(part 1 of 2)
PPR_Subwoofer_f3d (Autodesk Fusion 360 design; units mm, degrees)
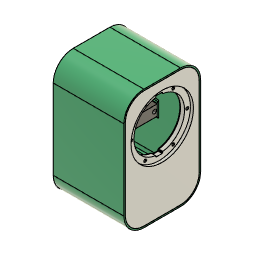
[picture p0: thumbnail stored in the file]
parameter "width" = 115
parameter "height" = 180
parameter "depth" = 94
parameter "cornerradius" = 30
parameter "driveroffset" = 60
parameter "length" = 150
parameter "width_1" = 84
parameter "cornerradius_1" = 40
parameter "length_1" = 155
parameter "width_2" = 89
parameter "cornerradius_2" = 44
sketch "Sketch1" plane through (0, 0, 0) normal (1, 0, 0) x axis (0, 1, 0)
  line L1 (85, 0) -> (30, 0)
  line L2 (115, 150) -> (115, 30)
  line L3 (30, 180) -> (85, 180)
  line L4 (0, 30) -> (0, 150)
  line L5 (10, 30) -> (10, 150)
  line L6 (85, 10) -> (30, 10)
  line L7 (105, 150) -> (105, 30)
  line L8 (30, 170) -> (85, 170)
  line L9 (85, 2) -> (30, 2)
  line L10 (113, 150) -> (113, 30)
  line L11 (30, 178) -> (85, 178)
  line L12 (2, 30) -> (2, 150)
  arc A1 centre (30, 150) radius 30 clockwise from (0, 150) to (30, 180)
  arc A2 centre (85, 150) radius 30 clockwise from (85, 180) to (115, 150)
  arc A3 centre (85, 30) radius 30 clockwise from (115, 30) to (85, 0)
  arc A4 centre (30, 30) radius 30 clockwise from (30, 0) to (0, 30)
  arc A5 centre (30, 30) radius 20 clockwise from (30, 10) to (10, 30)
  arc A6 centre (85, 30) radius 20 clockwise from (105, 30) to (85, 10)
  arc A7 centre (85, 150) radius 20 clockwise from (85, 170) to (105, 150)
  arc A8 centre (30, 150) radius 20 clockwise from (10, 150) to (30, 170)
  arc A9 centre (30, 30) radius 28 clockwise from (30, 2) to (2, 30)
  arc A10 centre (85, 30) radius 28 clockwise from (113, 30) to (85, 2)
  arc A11 centre (85, 150) radius 28 clockwise from (85, 178) to (113, 150)
  arc A12 centre (30, 150) radius 28 clockwise from (2, 150) to (30, 178)
  point P1 (0, 0)
  point P2 (0, 0)
  point P4 (0, 180)
  point P3 (115, 0)
  horizontal L1
  vertical L2
  horizontal L3
  vertical L4
  coincident P1 P2
  coincident P4 L3
  coincident P4 L4
  tangent L3 A1
  tangent L4 A1
  tangent L2 A2
  tangent L3 A2
  equal A1 A2
  coincident P3 L1
  coincident P3 L2
  tangent L1 A3
  tangent L2 A3
  equal A1 A3
  coincident P2 L1
  coincident P2 L4
  tangent L1 A4
  tangent L4 A4
  equal A1 A4
  dimension "d6" distance P2 P3 = 115 (= "width")
  dimension "d7" distance P2 P4 = 180 (= "height")
  dimension "d8" radius A1 = 30 (= "cornerradius")
  dimension "d9" = -10
  dimension "d10" = -2
extrude "Extrude1" new body sketch "Sketch1" profile of L5 A5 L7 L6 A6 L8 A7 A8 along normal blind 10
extrude "Extrude2" add sketch "Sketch1" along normal blind 94 (= "depth")
extrude "Extrude3" sketch "Sketch1" profile of L1 L2 L3 L4 A1 A2 A3 A4 A9 L10 L9 A10 L11 A11 A12 L12 blind 12
extrude "Extrude4" new body of existing geometry to an object bodies "Internal volume"
sketch "Sketch1" plane through (0, 0, 0) normal (1, 0, 0) x axis (0, 1, 0)
  line L1 (113, 150) -> (113, 30)
  line L2 (85, 2) -> (30, 2)
  line L3 (2, 30) -> (2, 150)
  line L4 (57.5, 2) -> (57.5, 178)
  line L5 (15.5, 118) -> (57.5, 118)
  line L6 (30, 178) -> (85, 178)
  line L7 (85, 2.2) -> (30, 2.2)
  line L8 (112.8, 150) -> (112.8, 30)
  line L9 (30, 177.8) -> (85, 177.8)
  line L10 (2.2, 30) -> (2.2, 150)
  line L11 (52.5, 157.8) -> (62.5, 157.8)
  line L12 (52.5, 78.2) -> (52.5, 157.8)
  line L13 (62.5, 78.2) -> (52.5, 78.2)
  line L14 (62.5, 157.8) -> (62.5, 78.2)
  line L15 (52.5, 78.2) -> (62.5, 157.8)
  line L16 (62.5, 78.2) -> (52.5, 157.8)
  arc A1 centre (30, 150) radius 28 clockwise from (2, 150) to (30, 178)
  arc A2 centre (85, 150) radius 28 clockwise from (85, 178) to (113, 150)
  arc A3 centre (85, 30) radius 28 clockwise from (113, 30) to (85, 2)
  arc A4 centre (30, 30) radius 28 clockwise from (30, 2) to (2, 30)
  circle C1 centre (57.5, 118) radius 46.8
  circle C2 centre (57.5, 118) radius 38
  circle C3 centre (15.5, 118) radius 1.35
  circle C4 centre (36.5, 81.6269) radius 1.35
  circle C5 centre (78.5, 81.6269) radius 1.35
  circle C6 centre (99.5, 118) radius 1.35
  circle C7 centre (78.5, 154.3731) radius 1.35
  circle C8 centre (36.5, 154.3731) radius 1.35
  arc A5 centre (30, 30) radius 27.8 clockwise from (30, 2.2) to (2.2, 30)
  arc A6 centre (85, 30) radius 27.8 clockwise from (112.8, 30) to (85, 2.2)
  arc A7 centre (85, 150) radius 27.8 clockwise from (85, 177.8) to (112.8, 150)
  arc A8 centre (30, 150) radius 27.8 clockwise from (2.2, 150) to (30, 177.8)
  point P21 (57.5, 2)
  point P22 (57.5, 118)
  point P24 (57.5, 118)
  point P25 (15.5, 118)
  point P26 (15.5, 118)
  point P20 (57.5, 178)
  point P50 (57.5, 118)
  point P23 (57.5, 118)
  point P48 (52.5, 78.2)
  point P49 (62.5, 78.2)
  point P47 (52.5, 157.8)
  midpoint L2 P21
  coincident L4 P22
  concentric C1 C2
  coincident P22 P24
  coincident P25 P26
  coincident P20 L6
  midpoint P20 L6
  horizontal L11
  perpendicular L11 L12
  parallel L11 L13
  parallel L12 L14
  coincident L15 P50
  coincident L16 P50
  coincident P23 P50
  dimension "d21" diameter C1 = 93.6
  dimension "d23" diameter C2 = 76
  dimension "d24" angle L4 L5 = 90
  dimension "d25" distance P24 P25 = 42 (= "( 84 / 2 ) * 1 mm")
  dimension "d26" diameter C3 = 2.7
  dimension "d36" = -0.2
  dimension "d37" distance L5 L6 = 60 (= "driveroffset")
  dimension "d180" distance P48 P49 = 10
  dimension "d181" distance P47 P48 = 79.6
  dimension "d28" C-Pattern1-Angle = 360
extrude "Extrude1" sketch "Sketch1" profile of C1 C2 C3 C4 C5 C6 C7 C8 L7 A5 A8 L9 A6 L8 A7 L10 L11 L12 L13 L14 blind 12
extrude "Extrude2" sketch "Sketch1" profile of C1 C2 C3 C4 C5 C6 C7 C8 blind -4.5
chamfer "Chamfer1" distance 0.8
sketch "Sketch1" plane through (0, 0, 0) normal (1, 0, 0) x axis (0, 1, 0)
  line L1 (0, 0.6) -> (4, 0.6)
  line L2 (4, 0) -> (0, 0)
  line L3 (-1.2, 4) -> (-1.2, 0)
  line L4 (0, 0) -> (0, 4)
  line L5 (-1.2, 0) -> (0, 0)
  line L6 (0, 0) -> (0, 0.6)
  line L7 (4, 0.6) -> (4, 0)
  line L8 (0, 4) -> (-1.2, 4)
  line L9 (-1.2, 0) -> (-1.2, 0.6)
  line L10 (-3.6, 2.3835) -> (-1.6, 0)
  line L11 (1.0702, 0) -> (-1.6, 0)
  line L12 (-1.2, 0) -> (-3.2, 2.3835)
  line L13 (-5.6, 0) -> (-3.6, 2.3835)
  line L14 (-4, 2.3835) -> (-6, 0)
  line L15 (-6, 0) -> (-5.6, 0)
  line L16 (-1.2, 0) -> (-1.6, 0)
  line L17 (-4, 2.3835) -> (-3.2, 2.3835)
  line L18 (-4, 2.9835) -> (-4, 2.3835)
  line L19 (-3.2, 2.9835) -> (-4, 2.9835)
  line L20 (-3.2, 2.3835) -> (-3.2, 2.9835)
  line L21 (-6, 0.4) -> (-6, 0)
  line L22 (-5.6644, 0.4) -> (-6, 0.4)
  line L23 (-1.2, 0.4) -> (-1.5356, 0.4)
  line L24 (-8.8, 2.3835) -> (-10.8, 0)
  line L25 (-10.4, 0) -> (-8.4, 2.3835)
  line L26 (-10.4644, 0.4) -> (-10.8, 0.4)
  line L27 (-10.8, 0) -> (-10.4, 0)
  line L28 (-6, 0) -> (-6.4, 0)
  line L29 (-8.4, 2.3835) -> (-6.4, 0)
  line L30 (-6, 0) -> (-8, 2.3835)
  line L31 (-6, 0.4) -> (-6.3356, 0.4)
  line L32 (-8, 2.3835) -> (-8, 2.9835)
  line L33 (-8, 2.9835) -> (-8.8, 2.9835)
  line L34 (-8.8, 2.9835) -> (-8.8, 2.3835)
  line L35 (-6, 2.4) -> (-6, 0.4)
  line L36 (-10.8, 4) -> (-10.8, 0)
  line L37 (-12, 0) -> (-12, 4)
  line L38 (-12, 0.6) -> (-16, 0.6)
  line L39 (-16, 0) -> (-12, 0)
  line L40 (-10.8, 0) -> (-12, 0)
  line L41 (-16, 0.6) -> (-16, 0)
  line L42 (-12, 4) -> (-10.8, 4)
  line L43 (-44.5, 10) -> (-44.5, 0)
  point P5 (0, 0)
  point P10 (0, 0)
  point P9 (0, 0)
  point P1 (0, 0)
  point P16 (-1.2, 0)
  point P13 (-3.6, 2.3835)
  point P15 (-3.2, 2.3835)
  point P19 (-4, 2.3835)
  point P17 (-5.6, 0)
  point P18 (-6, 0)
  point P11 (-1.6, 0)
  point P24 (-5.6644, 0.4)
  point P25 (-1.5356, 0.4)
  point P26 (-1.2, 0.4)
  point P2 (0, 0.6)
  point P47 (-12, 0.6)
  point P3 (4, 0)
  point P49 (-16, 0)
  point P4 (4, 0.6)
  point P46 (-16, 0.6)
  point P45 (-12, 0)
  point P6 (0, 4)
  point P44 (-12, 4)
  point P7 (-1.2, 4)
  point P43 (-10.8, 4)
  point P8 (-1.2, 0)
  point P42 (-10.8, 0)
  point P48 (-12, 0)
  point P12 (-1.2, 0.6)
  point P22 (-3.2, 2.9835)
  point P23 (-6, 0.4)
  point P37 (-6, 0.4)
  point P41 (-6, 2.4)
  point P50 (-44.5, 0)
  point P51 (-44.5, 10)
  horizontal L5
  vertical L3
  horizontal L8
  vertical L4
  coincident P5 P10
  horizontal L2
  vertical L7
  horizontal L1
  vertical L6
  coincident P9 P10
  coincident P1 P9
  vertical L9
  horizontal L11
  coincident L11 P16
  parallel L10 L12
  horizontal P13 P15
  horizontal P13 P19
  horizontal P17 P18
  equal L13 L14
  horizontal P9 P11
  coincident P9 L15
  horizontal L17
  vertical L18
  horizontal L19
  vertical L20
  coincident P19 L18
  vertical L21
  coincident L14 P24
  perpendicular L21 L22
  coincident L12 P25
  horizontal L23
  vertical P16 P26
  symmetric P2 L35 P47
  symmetric P3 L35 P49
  symmetric P4 L35 P46
  symmetric P5 L35 P45
  symmetric P6 L35 P44
  symmetric P7 L35 P43
  symmetric P8 L35 P42
  symmetric P9 L35 P48
  perpendicular L38 L43
  vertical L35
  dimension "d5" distance P6 P7 = 1.2
  dimension "d6_1" distance P5 P6 = 4
  dimension "d7_1" distance P3 P9 = 4
  dimension "d8_1" distance P2 P9 = 0.6
  dimension "d9_1" distance P8 P11 = 0.4
  dimension "d10_1" distance P8 P12 = 0.6
  dimension "d11_1" angle L10 L11 = 130
  dimension "d12_1" distance P11 P13 = 2
  dimension "d13_1" distance P13 P15 = 0.4
  dimension "d14_1" angle L5 L13 = 50
  dimension "d15_1" distance P13 P19 = 0.4
  dimension "d16_1" distance P15 P22 = 0.6
  dimension "d17_1" distance P18 P23 = 0.4
  dimension "d18_1" distance P16 P26 = 0.4
  dimension "d23_1" distance P37 P41 = 2
  dimension "d24_1" distance P50 P51 = 10
  dimension "d25_1" distance P10 L43 = 44.5 (= "width_2 / 2")
  dimension "d21_1" R-Pattern1-uDistance = -4.8
  dimension "d22" R-Pattern1-vDistance = 0
sketch "Sketch2" plane through (0, 0, 0) normal (0, 0, 1) x axis (1, 0, 0)
  line L1 (33.5, 0) -> (-33.5, 0)
  line L2 (33.5, -89) -> (-33.5, -89)
  line L3 (-77.5, -45) -> (-77.5, -44)
  line L4 (0, -89) -> (0, 0)
  line L5 (77.5, -45) -> (77.5, -44)
  arc A1 centre (-33.5, -44) radius 44 clockwise from (-77.5, -44) to (-33.5, 0)
  arc A2 centre (-33.5, -45) radius 44 clockwise from (-33.5, -89) to (-77.5, -45)
  arc A3 centre (33.5, -44) radius 44 clockwise from (33.5, 0) to (77.5, -44)
  arc A4 centre (33.5, -45) radius 44 clockwise from (77.5, -45) to (33.5, -89)
  point P4 (0, 0)
  point P1 (0, 0)
  point P3 (33.5, 0)
  point P6 (33.5, -89)
  point P2 (-33.5, 0)
  point P5 (-33.5, -89)
  point P9 (0, 0)
  point P12 (0, 0)
  point P13 (0, -89)
  point P15 (33.5, 0)
  point P19 (33.5, -89)
  point P7 (-77.5, -44)
  point P16 (77.5, -44)
  point P8 (-77.5, -45)
  point P17 (77.5, -45)
  horizontal L1
  midpoint L1 P4
  coincident P1 P4
  horizontal L2
  vertical P3 P6
  vertical P2 P5
  vertical L3
  tangent L3 A1
  tangent L3 A2
  tangent L2 A2
  coincident P9 P12
  midpoint L2 P13
  symmetric P2 L4 P15
  symmetric P5 L4 P19
  symmetric P7 L4 P16
  symmetric P8 L4 P17
  symmetric A1 L4 A3
  symmetric A2 L4 A4
  dimension "d62" distance P2 P3 = 67 (= "length_1 - cornerradius_2 * 2")
  dimension "d63" distance L1 L2 = 89 (= "width_2")
  dimension "d64" distance L3 P9 = 77.5 (= "length_1 / 2")
  dimension "d65" distance P7 P9 = 44 (= "cornerradius_2")
  dimension "d66" distance L2 P8 = 44 (= "cornerradius_2")
sweep "Sweep1" sketch "Sketch1" TwistAngle 0 TaperAngle 0 bodies "Suspension"
chamfer "Chamfer2" distance 0.4 Rotate Angle 50
chamfer "Chamfer3" distance 0.4
sketch "Sketch1" plane through (0, 0, 0) normal (1, 0, 0) x axis (0, 1, 0)
  line L1 (0, 0) -> (0, 4)
  line L2 (0, 0.6) -> (4, 0.6)
  line L3 (-12, 0) -> (-12, 4)
  line L4 (-12, 0.6) -> (-16, 0.6)
  line L5 (-44.5, 10) -> (-44.5, 0)
  line L6 (0.15, 0.6) -> (0.15, 4)
  line L7 (-12.15, 0.6) -> (-12.15, 4)
  line L8 (2.65, 0.6) -> (0.15, 0.6)
  line L9 (2.65, 10.6) -> (2.65, 0.6)
  line L10 (0.15, 10.6) -> (2.65, 10.6)
  line L11 (0.15, 0.6) -> (0.15, 10.6)
  line L12 (10.65, 0.6) -> (2.65, 0.6)
  line L13 (10.65, 3.6) -> (10.65, 0.6)
  line L14 (2.65, 3.6) -> (10.65, 3.6)
  line L15 (2.65, 0.6) -> (2.65, 3.6)
  line L16 (-15.15, 0.6) -> (-12.15, 0.6)
  line L17 (-15.15, 10.6) -> (-15.15, 0.6)
  line L18 (-12.15, 10.6) -> (-15.15, 10.6)
  line L19 (-12.15, 0.6) -> (-12.15, 10.6)
  line L20 (-50, 0.6) -> (-12.15, 0.6)
  line L21 (-50, 2.6) -> (-50, 0.6)
  line L22 (-12.15, 2.6) -> (-50, 2.6)
  line L23 (-12.15, 0.6) -> (-12.15, 2.6)
  line L24 (-44.5, 2.6) -> (-15.15, 2.6)
  line L25 (-44.5, 10.6) -> (-44.5, 2.6)
  line L26 (-15.15, 10.6) -> (-44.5, 10.6)
  line L27 (-15.15, 2.6) -> (-15.15, 10.6)
  point P13 (0.15, 0.6)
  point P12 (0.15, 4)
  point P14 (0, 4)
  point P16 (-12.15, 0.6)
  point P15 (-12.15, 4)
  point P17 (-12, 4)
  point P32 (-44.5, 10.6)
  point P30 (-15.15, 2.6)
  point P18 (2.65, 0.6)
  point P20 (0.15, 10.6)
  point P21 (10.65, 0.6)
  point P23 (2.65, 3.6)
  point P24 (-15.15, 0.6)
  point P26 (-12.15, 10.6)
  point P29 (-12.15, 2.6)
  coincident L2 P13
  perpendicular L2 L6
  horizontal P12 P14
  coincident L4 P16
  perpendicular L4 L7
  horizontal P15 P17
  horizontal L8
  vertical L9
  horizontal L10
  vertical L11
  horizontal L12
  vertical L13
  horizontal L14
  vertical L15
  horizontal L16
  vertical L17
  horizontal L18
  vertical L19
  horizontal L20
  vertical L21
  horizontal L22
  vertical L23
  horizontal L24
  vertical L25
  horizontal L26
  vertical L27
  coincident L5 P32
  coincident L22 P30
  coincident L17 P30
  collinear L18 L26
  dimension "d77" distance L1 L6 = 0.15
  dimension "d78" distance L3 L7 = 0.15
  dimension "d79" distance P13 P18 = 2.5
  dimension "d80" distance P13 P20 = 10
  dimension "d81" distance P18 P21 = 8
  dimension "d82" distance P18 P23 = 3
  dimension "d83" distance P16 P24 = 3
  dimension "d84" distance P16 P26 = 10
  dimension "d85" distance P16 P29 = 2
sweep "Sweep1" sketch "Sketch1" TwistAngle 0 TaperAngle 0 bodies "Ring Piece", "Center Piece"
sketch "Sketch2" plane through (0, 0, 0.6) normal (0, 0, -1) x axis (1, 0, 0)
  line L1 (-33.5, -0.15) -> (33.5, -0.15)
  line L2 (-77.65, 45) -> (-77.65, 44)
  line L3 (33.5, 89.15) -> (-33.5, 89.15)
  line L4 (77.65, 44) -> (77.65, 45)
  line L5 (88.15, 45) -> (88.15, 44)
  line L6 (-33.5, 99.65) -> (33.5, 99.65)
  line L7 (-88.15, 44) -> (-88.15, 45)
  line L8 (33.5, -10.65) -> (-33.5, -10.65)
  line L9 (33.5, -10.65) -> (-33.5, -10.65)
  line L10 (0, -10.65) -> (0, 110.15)
  line L11 (-88.15, 44.5) -> (88.15, 44.5)
  arc A1 centre (33.5, 44) radius 44.15 clockwise from (77.65, 44) to (33.5, -0.15)
  arc A2 centre (-33.5, 44) radius 44.15 clockwise from (-33.5, -0.15) to (-77.65, 44)
  arc A3 centre (-33.5, 45) radius 44.15 clockwise from (-77.65, 45) to (-33.5, 89.15)
  arc A4 centre (33.5, 45) radius 44.15 clockwise from (33.5, 89.15) to (77.65, 45)
  arc A5 centre (33.5, 45) radius 54.65 clockwise from (33.5, 99.65) to (88.15, 45)
  arc A6 centre (-33.5, 45) radius 54.65 clockwise from (-88.15, 45) to (-33.5, 99.65)
  arc A7 centre (-33.5, 44) radius 54.65 clockwise from (-33.5, -10.65) to (-88.15, 44)
  arc A8 centre (33.5, 44) radius 54.65 clockwise from (88.15, 44) to (33.5, -10.65)
  circle C1 centre (-35.65, 96) radius 1.7
  circle C2 centre (-84.5, 44.5) radius 1.7
  circle C3 centre (-35.65, -7) radius 1.7
  circle C4 centre (84.5, 44.5) radius 1.7
  circle C5 centre (35.65, 96) radius 1.7
  circle C6 centre (35.65, -7) radius 1.7
  point P25 (0, -10.65)
  point P26 (88.15, 44.5)
  point P27 (-88.15, 44.5)
  point P29 (-84.5, 44.5)
  point P28 (-35.65, 96)
  midpoint L9 P25
  perpendicular L9 L10
  midpoint L5 P26
  midpoint L7 P27
  coincident L11 P29
  symmetric L11 C1 C3
  symmetric L10 C1 C5
  symmetric L10 C2 C4
  symmetric L10 C3 C6
  dimension "d92" diameter C1 = 3.4
  dimension "d93" distance L10 P28 = 35.65 (= "length_1 * 0.23")
  dimension "d94" distance L11 P28 = 51.5 (= "width_2 / 2 + 7 mm")
  dimension "d95" diameter C2 = 3.4
  dimension "d96" distance L10 P29 = 84.5 (= "length_1 / 2 + 7 mm")
extrude "Extrude1" cut sketch "Sketch2" profile of C1 C2 C3 C4 C5 C6 to an object
chamfer "Chamfer1" distance 0.8 Rotate Angle 55
sketch "Sketch3" plane through (0, 0, 0) normal (0, 0, 1) x axis (-1, 0, 0)
  line L1 (33.5, 15.15) -> (-33.5, 15.15)
  line L2 (62.35, 45) -> (62.35, 44)
  line L3 (-33.5, 73.85) -> (33.5, 73.85)
  line L4 (-62.35, 44) -> (-62.35, 45)
  line L5 (-62.35, 44.5) -> (62.35, 44.5)
  line L6 (0, 73.85) -> (0, 15.15)
  line L7 (62.35, 44.5) -> (0, 44.5)
  circle C1 centre (0, 44.5) radius 1.35
  circle C2 centre (0, 44.5) radius 3.25
  circle C3 centre (31.175, 44.5) radius 1.35
  circle C4 centre (31.175, 44.5) radius 3.25
  arc A1 centre (33.5, 44) radius 28.85 clockwise from (62.35, 44) to (33.5, 15.15)
  arc A2 centre (33.5, 45) radius 28.85 clockwise from (33.5, 73.85) to (62.35, 45)
  arc A3 centre (-33.5, 45) radius 28.85 clockwise from (-62.35, 45) to (-33.5, 73.85)
  arc A4 centre (-33.5, 44) radius 28.85 clockwise from (-33.5, 15.15) to (-62.35, 44)
  circle C5 centre (-31.175, 44.5) radius 3.25
  circle C6 centre (-31.175, 44.5) radius 1.35
  point P18 (62.35, 44.5)
  point P19 (-62.35, 44.5)
  point P5 (31.175, 44.5)
  point P20 (0, 15.15)
  point P21 (0, 73.85)
  point P22 (0, 44.5)
  point P2 (0, 44.5)
  point P23 (0, 44.5)
  point P24 (31.175, 44.5)
  point P25 (31.175, 44.5)
  point P4 (31.175, 44.5)
  concentric C1 C2
  concentric C3 C4
  midpoint L2 P18
  midpoint L4 P19
  coincident P5 L5
  midpoint L1 P20
  midpoint L3 P21
  midpoint L6 P22
  coincident P2 P22
  coincident P22 P23
  midpoint L7 P24
  coincident P5 P25
  coincident P4 P24
  symmetric C3 L6 C6
  symmetric C4 L6 C5
  dimension "d101" diameter C1 = 2.7
  dimension "d102" diameter C2 = 6.5
  dimension "d103" diameter C3 = 2.7
  dimension "d104" diameter C4 = 6.5
extrude "Extrude2" sketch "Sketch3" profile of C1 C2 C3 C4 C5 C6 blind 2
extrude "Extrude3" cut of existing geometry to an object offset -0.6
sketch "Sketch4" plane through (0, 0, 3.6) normal (0, 0, 1) x axis (-1, 0, 0)
  line L1 (33.5, -10.65) -> (-33.5, -10.65)
  line L2 (88.15, 45) -> (88.15, 44)
  line L3 (-33.5, 99.65) -> (33.5, 99.65)
  line L4 (-88.15, 44) -> (-88.15, 45)
  line L5 (-80.15, 45) -> (-80.15, 44)
  line L6 (33.5, 91.65) -> (-33.5, 91.65)
  line L7 (80.15, 44) -> (80.15, 45)
  line L8 (-33.5, -2.65) -> (33.5, -2.65)
  line L9 (33.5, -2.65) -> (-33.5, -2.65)
  line L10 (80.15, 45) -> (80.15, 44)
  line L11 (-33.5, 91.65) -> (33.5, 91.65)
  line L12 (-80.15, 44) -> (-80.15, 45)
  line L13 (-77.65, 45) -> (-77.65, 44)
  line L14 (33.5, 89.15) -> (-33.5, 89.15)
  line L15 (77.65, 44) -> (77.65, 45)
  line L16 (-33.5, -0.15) -> (33.5, -0.15)
  circle C1 centre (-35.65, 96) radius 1.7
  circle C2 centre (84.5, 44.5) radius 1.7
  circle C3 centre (-84.5, 44.5) radius 1.7
  circle C4 centre (35.65, -7) radius 1.7
  circle C5 centre (35.65, 96) radius 1.7
  circle C6 centre (-35.65, -7) radius 1.7
  arc A1 centre (-33.5, 44) radius 54.65 clockwise from (-33.5, -10.65) to (-88.15, 44)
  arc A2 centre (33.5, 44) radius 54.65 clockwise from (88.15, 44) to (33.5, -10.65)
  arc A3 centre (33.5, 45) radius 54.65 clockwise from (33.5, 99.65) to (88.15, 45)
  arc A4 centre (-33.5, 45) radius 54.65 clockwise from (-88.15, 45) to (-33.5, 99.65)
  arc A5 centre (-33.5, 45) radius 46.65 clockwise from (-80.15, 45) to (-33.5, 91.65)
  arc A6 centre (33.5, 45) radius 46.65 clockwise from (33.5, 91.65) to (80.15, 45)
  arc A7 centre (33.5, 44) radius 46.65 clockwise from (80.15, 44) to (33.5, -2.65)
  arc A8 centre (-33.5, 44) radius 46.65 clockwise from (-33.5, -2.65) to (-80.15, 44)
  arc A9 centre (-33.5, 44) radius 46.65 clockwise from (-33.5, -2.65) to (-80.15, 44)
  arc A10 centre (33.5, 44) radius 46.65 clockwise from (80.15, 44) to (33.5, -2.65)
  arc A11 centre (33.5, 45) radius 46.65 clockwise from (33.5, 91.65) to (80.15, 45)
  arc A12 centre (-33.5, 45) radius 46.65 clockwise from (-80.15, 45) to (-33.5, 91.65)
  arc A13 centre (-33.5, 45) radius 44.15 clockwise from (-77.65, 45) to (-33.5, 89.15)
  arc A14 centre (33.5, 45) radius 44.15 clockwise from (33.5, 89.15) to (77.65, 45)
  arc A15 centre (33.5, 44) radius 44.15 clockwise from (77.65, 44) to (33.5, -0.15)
  arc A16 centre (-33.5, 44) radius 44.15 clockwise from (-33.5, -0.15) to (-77.65, 44)
extrude "Extrude4" new body sketch "Sketch4" profile of L13 A13 L14 A14 L15 A15 L16 A16 along normal blind 20 bodies "Cut-out"
sketch "Sketch5" plane through (0, 0, 10.6) normal (0, 0, 1) x axis (-1, 0, 0)
  line L1 (33.5, -2.65) -> (-33.5, -2.65)
  line L2 (80.15, 45) -> (80.15, 44)
  line L3 (-33.5, 91.65) -> (33.5, 91.65)
  line L4 (-80.15, 44) -> (-80.15, 45)
  line L5 (-77.65, 45) -> (-77.65, 44)
  line L6 (33.5, 89.15) -> (-33.5, 89.15)
  line L7 (77.65, 44) -> (77.65, 45)
  line L8 (-33.5, -0.15) -> (33.5, -0.15)
  arc A1 centre (-33.5, 44) radius 46.65 clockwise from (-33.5, -2.65) to (-80.15, 44)
  arc A2 centre (33.5, 44) radius 46.65 clockwise from (80.15, 44) to (33.5, -2.65)
  arc A3 centre (33.5, 45) radius 46.65 clockwise from (33.5, 91.65) to (80.15, 45)
  arc A4 centre (-33.5, 45) radius 46.65 clockwise from (-80.15, 45) to (-33.5, 91.65)
  arc A5 centre (-33.5, 45) radius 44.15 clockwise from (-77.65, 45) to (-33.5, 89.15)
  arc A6 centre (33.5, 45) radius 44.15 clockwise from (33.5, 89.15) to (77.65, 45)
  arc A7 centre (33.5, 44) radius 44.15 clockwise from (77.65, 44) to (33.5, -0.15)
  arc A8 centre (-33.5, 44) radius 44.15 clockwise from (-33.5, -0.15) to (-77.65, 44)
copy_paste_bodies "CopyPasteBodies1"
extrude "Extrude1" sketch "Sketch5" against normal blind 54.974
sketch "Sketch1" plane through (0, 0, 0) normal (1, 0, 0) x axis (0, 1, 0)
  line L1 (-44.5, 10) -> (-44.5, 0)
  line L2 (-12, 0.6) -> (-16, 0.6)
  line L3 (-12, 0) -> (-12, 4)
  line L4 (0, 0) -> (0, 4)
  line L5 (0, 0.6) -> (4, 0.6)
  line L6 (-12.15, 0) -> (-12.15, 4)
  line L7 (0.15, 0) -> (0.15, 4)
  line L8 (4.15, 0.6) -> (0.15, 0.6)
  line L9 (4.15, 10.6) -> (4.15, 0.6)
  line L10 (0.15, 10.6) -> (4.15, 10.6)
  line L11 (0.15, 0.6) -> (0.15, 10.6)
  line L12 (11.15, 0.6) -> (4.15, 0.6)
  line L13 (11.15, 3.1) -> (11.15, 0.6)
  line L14 (4.15, 3.1) -> (11.15, 3.1)
  line L15 (4.15, 0.6) -> (4.15, 3.1)
  line L16 (-44.5, 0.6) -> (-12.15, 0.6)
  line L17 (-44.5, 10.6) -> (-44.5, 0.6)
  line L18 (-12.15, 10.6) -> (-44.5, 10.6)
  line L19 (-12.15, 0.6) -> (-12.15, 10.6)
  line L20 (-15.15, 10.6) -> (-44.5, 10.6)
  line L21 (-15.15, 2.2) -> (-15.15, 10.6)
  line L22 (-44.5, 2.2) -> (-15.15, 2.2)
  line L23 (-44.5, 10.6) -> (-44.5, 2.2)
  point P16 (0.15, 0.6)
  point P17 (4.15, 0.6)
  point P19 (0.15, 10.6)
  point P20 (11.15, 0.6)
  point P22 (4.15, 3.1)
  point P23 (-12.15, 0.6)
  point P26 (-12.15, 10.6)
  horizontal L8
  vertical L9
  horizontal L10
  vertical L11
  coincident L5 P16
  coincident L7 P16
  horizontal L12
  vertical L13
  horizontal L14
  vertical L15
  horizontal L16
  vertical L17
  horizontal L18
  vertical L19
  collinear L1 L17
  horizontal L20
  vertical L21
  horizontal L22
  vertical L23
  collinear L6 L19
  collinear L2 L16
  dimension "d28_1" = 0.15
  dimension "d29_1" = -0.15
  dimension "d30_1" distance P16 P17 = 4
  dimension "d31_1" distance P16 P19 = 10
  dimension "d32_1" distance P17 P20 = 7
  dimension "d33_1" distance P17 P22 = 2.5
  dimension "d34_1" distance P23 P26 = 10
  dimension "d35_1" distance L19 L21 = 3
  dimension "d36_1" distance L16 L22 = 1.6
sketch "Sketch6" plane through (0, -15.15, 0) normal (0, -1, 0) x axis (1, 0, 0)
  line L1 (-33.5, 2.6) -> (-33.5, 10.6)
  line L2 (33.5, 2.6) -> (-33.5, 2.6)
  line L3 (33.5, 10.6) -> (33.5, 2.6)
  line L4 (-33.5, 10.6) -> (33.5, 10.6)
  line L5 (33.5, 6.6) -> (-33.5, 6.6)
  circle C1 centre (0, 6.6) radius 1.75
  point P6 (-33.5, 6.6)
  point P7 (33.5, 6.6)
  point P8 (0, 6.6)
  midpoint L1 P6
  midpoint L3 P7
  midpoint L5 P8
  dimension "d115" diameter C1 = 3.5
extrude "Extrude5" cut sketch "Sketch6" profile of C1 to an object
path_pattern "PathPattern1" countU 16 PathPatternDelta 223.516
align "Align1"
sketch "Sketch7" plane through (0, 0, 0.6) normal (0, 0, -1) x axis (1, 0, 0)
  line L1 (65.35, 45) -> (65.35, 44)
  line L2 (-33.5, 76.85) -> (33.5, 76.85)
  line L3 (-65.35, 44) -> (-65.35, 45)
  line L4 (33.5, 12.15) -> (-33.5, 12.15)
  line L5 (-61.2, 44) -> (-61.2, 45)
  line L6 (33.5, 16.3) -> (-33.5, 16.3)
  line L7 (61.2, 45) -> (61.2, 44)
  line L8 (-33.5, 72.7) -> (33.5, 72.7)
  arc A1 centre (33.5, 44) radius 31.85 clockwise from (65.35, 44) to (33.5, 12.15)
  arc A2 centre (33.5, 45) radius 31.85 clockwise from (33.5, 76.85) to (65.35, 45)
  arc A3 centre (-33.5, 45) radius 31.85 clockwise from (-65.35, 45) to (-33.5, 76.85)
  arc A4 centre (-33.5, 44) radius 31.85 clockwise from (-33.5, 12.15) to (-65.35, 44)
  arc A5 centre (-33.5, 44) radius 27.7 clockwise from (-33.5, 16.3) to (-61.2, 44)
  arc A6 centre (33.5, 44) radius 27.7 clockwise from (61.2, 44) to (33.5, 16.3)
  arc A7 centre (33.5, 45) radius 27.7 clockwise from (33.5, 72.7) to (61.2, 45)
  arc A8 centre (-33.5, 45) radius 27.7 clockwise from (-61.2, 45) to (-33.5, 72.7)
  dimension "d120" = -4.15
extrude "Extrude6" new body sketch "Sketch7" against normal blind 4
extrude "Extrude7" new body sketch "Sketch7" profile of L8 L7 A5 L6 A8 A7 A6 L5 along normal blind 6 bodies "Center piece 2"
chamfer "Chamfer2" distance 3.8 Rotate Angle 45
sketch "Sketch8" plane through (0, 0, 4.6) normal (0, 0, 1) x axis (-1, 0, 0)
  line L1 (33.5, 12.15) -> (-33.5, 12.15)
  line L2 (65.35, 45) -> (65.35, 44)
  line L3 (-33.5, 76.85) -> (33.5, 76.85)
  line L4 (-65.35, 44) -> (-65.35, 45)
  line L5 (0, 76.85) -> (0, 12.15)
  line L6 (40, 54.5) -> (-40, 54.5)
  line L7 (40, 34.5) -> (40, 54.5)
  line L8 (-40, 34.5) -> (40, 34.5)
  line L9 (-40, 54.5) -> (-40, 34.5)
  line L10 (40, 34.5) -> (-40, 54.5)
  line L11 (-40, 34.5) -> (40, 54.5)
  arc A1 centre (33.5, 44) radius 31.85 clockwise from (65.35, 44) to (33.5, 12.15)
  arc A2 centre (33.5, 45) radius 31.85 clockwise from (33.5, 76.85) to (65.35, 45)
  arc A3 centre (-33.5, 45) radius 31.85 clockwise from (-65.35, 45) to (-33.5, 76.85)
  arc A4 centre (-33.5, 44) radius 31.85 clockwise from (-33.5, 12.15) to (-65.35, 44)
  point P14 (0, 12.15)
  point P15 (0, 76.85)
  point P20 (0, 44.5)
  point P18 (40, 34.5)
  point P19 (-40, 34.5)
  point P17 (40, 54.5)
  midpoint L1 P14
  midpoint L3 P15
  horizontal L6
  perpendicular L6 L7
  parallel L6 L8
  parallel L7 L9
  coincident L10 P20
  coincident L11 P20
  midpoint L5 P20
  dimension "d127" distance P18 P19 = 80
  dimension "d128" distance P17 P18 = 20
extrude "Extrude8" cut sketch "Sketch8" profile of L6 L7 L8 L9 to an object offset -2
combine "Combine2"
copy_paste_bodies "CopyPasteBodies2"
extrude "Extrude9" cut of existing geometry to an object
position "Position6"
align "Align4"
position "Position7"
work_plane "WorkPlane1"
sketch "Sketch2" plane through (56, 57.5, 90) normal (0, 0, -1) x axis (1, 0, 0)
  line L1 (38, 47.5) -> (-46, 47.5)
  line L2 (-46, 47.5) -> (38, 47.5)
  line L3 (38, -47.5) -> (-46, -47.5)
  line L4 (-46, -47.5) -> (38, -47.5)
  line L5 (-46, 47.5) -> (-46, 27.5)
  line L6 (-46, 47.5) -> (-46, 27.5)
  line L7 (-46, -27.5) -> (-46, 27.5)
  line L8 (-46, -27.5) -> (-46, -47.5)
  line L9 (-46, -27.5) -> (-46, -47.5)
  line L10 (-46, 27.5) -> (-46, -27.5)
  line L11 (-21, 37.5) -> (-35.2815, 47.5)
  line L12 (-16.4004, 47.5) -> (-35.2815, 47.5)
  line L13 (-21, 48.846) -> (-21, 37.5)
  line L14 (-18, 37.5) -> (-21, 37.5)
  line L15 (-18, 47.5) -> (-18, 37.5)
  line L16 (-21, 47.5) -> (-18, 47.5)
  line L17 (-21, 37.5) -> (-21, 47.5)
  line L18 (-3, 47.5) -> (-18, 47.5)
  line L19 (-3, 45.5) -> (-3, 47.5)
  line L20 (-18, 45.5) -> (-3, 45.5)
  line L21 (-18, 47.5) -> (-18, 45.5)
  line L22 (-13, 45.5) -> (-18, 45.5)
  line L23 (-13, 37.5) -> (-13, 45.5)
  line L24 (-18, 37.5) -> (-13, 37.5)
  line L25 (-18, 45.5) -> (-18, 37.5)
  line L26 (-4, 47.5) -> (-4, -47.5)
  line L27 (26, 0) -> (-4, 0)
  line L28 (-2.85, 45.35) -> (-17.85, 45.35)
  line L29 (-2.85, 0) -> (-2.85, 45.35)
  line L30 (-17.85, 0) -> (-2.85, 0)
  line L31 (-17.85, 45.35) -> (-17.85, 0)
  point P10 (-35.2815, 47.5)
  point P23 (-4, -47.5)
  point P24 (-4, 47.5)
  point P25 (-4, 0)
  point P29 (-2.85, 0)
  point P11 (-21, 37.5)
  point P14 (-18, 37.5)
  point P15 (-18, 47.5)
  point P17 (-3, 47.5)
  point P19 (-18, 45.5)
  point P20 (-13, 45.5)
  point P26 (26, 0)
  point P27 (-17.85, 45.35)
  point P28 (-2.85, 45.35)
  horizontal L12
  coincident L2 P10
  perpendicular L2 L13
  horizontal L14
  vertical L15
  horizontal L16
  vertical L17
  horizontal L18
  vertical L19
  horizontal L20
  vertical L21
  collinear L1 L18
  horizontal L22
  vertical L23
  horizontal L24
  vertical L25
  collinear L14 L24
  midpoint L3 P23
  midpoint L2 P24
  midpoint L26 P25
  perpendicular L26 L27
  horizontal L28
  vertical L29
  horizontal L30
  vertical L31
  coincident L27 P29
  dimension "d50" angle L11 L12 = 35
  dimension "d51" distance P11 L12 = 10
  dimension "d52" distance L6 P11 = 25
  dimension "d53" distance P11 P14 = 3
  dimension "d54" distance P15 P17 = 15
  dimension "d55" distance P15 P19 = 2
  dimension "d56" distance P19 P20 = 5
  dimension "d57" distance P25 P26 = 30
  dimension "d58" distance P27 P28 = 15
  dimension "d59" distance L20 L28 = 0.15
  dimension "d60" distance L25 L31 = 0.15
extrude "Extrude5" new body sketch "Sketch2" profile of L1 L2 L11 L13 L14 L15 L16 L17 L18 L19 L20 L21 L22 L23 L24 L25 L28 L31 distance 10 bodies "lug"
extrude "Extrude6" cut sketch "Sketch2" profile of L15 L20 L22 L23 L24 L25 L28 L31 distance 8.3
extrude "Extrude7" new body sketch "Sketch2" profile of L23 L24 L28 L29 L30 L31 distance 8 bodies "brace"
sketch "Sketch3" plane through (53.15, 0, 0) normal (1, 0, 0) x axis (0, 1, 0)
  line L1 (12.15, 82) -> (12.15, 98)
  line L2 (57.5, 82) -> (12.15, 82)
  line L3 (57.5, 98) -> (57.5, 82)
  line L4 (12.15, 98) -> (57.5, 98)
  line L5 (16.15, 82) -> (16.15, 98)
  line L6 (12.15, 90) -> (16.15, 90)
  circle C1 centre (16.15, 90) radius 1.35
  circle C2 centre (16.15, 90) radius 1.7
  circle C3 centre (16.15, 90) radius 3
  point P6 (16.15, 98)
  point P7 (16.15, 82)
  point P8 (16.15, 90)
  point P9 (12.15, 90)
  point P10 (16.15, 90)
  point P11 (16.15, 90)
  coincident L4 P6
  coincident L2 P7
  perpendicular L2 L5
  coincident L5 P8
  coincident L1 P9
  perpendicular L1 L6
  midpoint L5 P8
  coincident P8 P10
  coincident P8 P11
  concentric C1 C3
  dimension "d138" distance L1 L5 = 4
  dimension "d139" diameter C1 = 2.7
  dimension "d140" diameter C2 = 3.4
  dimension "d141" diameter C3 = 6
extrude "Extrude8" cut sketch "Sketch3" profile of C1 C2 to an object
extrude "Extrude9" cut sketch "Sketch3" profile of C2 C3 to an object offset -3
extrude "Extrude10" sketch "Sketch3" profile of C1 blind -15
chamfer "Chamfer1" distance 0.8
chamfer "Chamfer2" distance 0.8
mirror "Mirror1" mirrorStitchTolerance 0.1 bodies "lug (1)", "brace (1)"
combine "Combine3" bodies "brace (1)"
combine "Combine4" bodies "lug", "lug (1)"
combine "Combine2"
sketch "Sketch4" plane through (0, 0, 0) normal (-1, 0, 0) x axis (0, -1, 0)
  line L1 (0, 150) -> (0, 30)
  line L2 (-85, 180) -> (-30, 180)
  line L3 (-115, 30) -> (-115, 150)
  line L4 (-30, 0) -> (-85, 0)
  line L5 (-115, 30) -> (-85, 0)
  line L6 (-95.4038, 16.0607) -> (-98.9393, 19.5962)
  line L7 (-97.1716, 17.8284) -> (-100, 15)
  line L8 (-98.9393, 12.5251) -> (-102.4749, 16.0607)
  line L9 (-102.4749, 18.182) -> (-101.0607, 19.5962)
  line L10 (-96.818, 12.5251) -> (-95.4038, 13.9393)
  curve K1 (-94.8168, 20.1832) -> (-94.0986, 9.0986)
  curve K2 (-93.2766, 10.4875) -> (-94.9206, 7.7097)
  curve K3 (-96.7231, 22.0896) -> (-92.9104, 18.2769)
  curve K4 (-94.8168, 20.1832) -> (-105.9014, 20.9014)
  curve K5 (-104.5125, 21.7234) -> (-107.2903, 20.0794)
  curve K6 (-92.9104, 18.2769) -> (-96.7231, 22.0896)
  line L11 (-12.85, 56.5) -> (-12.85, 123.5)
  line L12 (-58, 12.35) -> (-57, 12.35)
  line L13 (-102.15, 123.5) -> (-102.15, 56.5)
  line L14 (-57, 167.65) -> (-58, 167.65)
  arc A1 centre (-30, 30) radius 30 clockwise from (0, 30) to (-30, 0)
  arc A2 centre (-30, 150) radius 30 clockwise from (-30, 180) to (0, 150)
  arc A3 centre (-85, 150) radius 30 clockwise from (-115, 150) to (-85, 180)
  arc A4 centre (-85, 30) radius 30 clockwise from (-85, 0) to (-115, 30)
  arc A5 centre (-100, 18.5355) radius 1.5 clockwise from (-101.0607, 19.5962) to (-98.9393, 19.5962)
  arc A6 centre (-101.4142, 17.1213) radius 1.5 clockwise from (-102.4749, 16.0607) to (-102.4749, 18.182)
  arc A7 centre (-97.8787, 13.5858) radius 1.5 clockwise from (-96.818, 12.5251) to (-98.9393, 12.5251)
  arc A8 centre (-96.4645, 15) radius 1.5 clockwise from (-95.4038, 16.0607) to (-95.4038, 13.9393)
  arc A9 centre (-57, 56.5) radius 44.15 clockwise from (-12.85, 56.5) to (-57, 12.35)
  arc A10 centre (-58, 56.5) radius 44.15 clockwise from (-58, 12.35) to (-102.15, 56.5)
  arc A11 centre (-58, 123.5) radius 44.15 clockwise from (-102.15, 123.5) to (-58, 167.65)
  arc A12 centre (-57, 123.5) radius 44.15 clockwise from (-57, 167.65) to (-12.85, 123.5)
  point P12 (-85, 0)
  point P14 (-85, 0)
  point P11 (-115, 30)
  point P15 (-115, 30)
  point P18 (-100, 15)
  point P19 (-97.1716, 17.8284)
  point P16 (-100, 20.6569)
  point P17 (-94.3431, 15)
  point P32 (-94.0986, 9.0986)
  point P33 (-94.8168, 20.1832)
  point P38 (-105.9014, 20.9014)
  point P39 (-94.8168, 20.1832)
  point P34 (-94.9206, 7.7097)
  point P40 (-107.2903, 20.0794)
  point P35 (-93.2766, 10.4875)
  point P41 (-104.5125, 21.7234)
  point P36 (-92.9104, 18.2769)
  point P42 (-96.7231, 22.0896)
  point P37 (-96.7231, 22.0896)
  point P43 (-92.9104, 18.2769)
  coincident P12 P14
  coincident P11 P15
  parallel L5 L6
  midpoint L5 P18
  perpendicular L5 L7
  parallel L6 L8
  coincident L6 P19
  coincident P16 L6
  coincident P16 L9
  tangent L6 A5
  tangent L9 A5
  tangent L8 A6
  tangent L9 A6
  equal A5 A6
  tangent L8 A7
  tangent L10 A7
  equal A5 A7
  coincident P17 L6
  coincident P17 L10
  tangent L6 A8
  tangent L10 A8
  equal A5 A8
  parallel L9 L10
  midpoint P32 K2
  midpoint P33 K3
  parallel L6 K3
  coincident L5 P32
  coincident L7 P33
  symmetric L7 P32 P38
  symmetric L7 P33 P39
  symmetric L7 P34 P40
  symmetric L7 P35 P41
  symmetric L7 P36 P42
  symmetric L7 P37 P43
  dimension "d153" distance P16 P17 = 8
  dimension "d155" distance L5 L6 = 4
  dimension "d156" radius A5 = 1.5
  dimension "d157" distance L6 L8 = 5
  dimension "d158" distance L7 L9 = 4
extrude "Extrude11" add sketch "Sketch4" profile of L5 L6 L8 L9 L10 A5 A6 A7 A8 K1 K4 against normal blind 40
fillet "Fillet1" radius 7
work_plane "WorkPlane2" RotateAngle 0
sketch "Sketch5" plane through (0, 98.5858, 16.4142) normal (0, 0.7071, 0.7071) x axis (0, -0.7071, 0.7071)
  line L1 (0, 27.0443) -> (0, 0)
  curve K1 (3.2223, 45.4963) -> (0, 27.0443)
  curve K2 (0, 29.9889) -> (0, 24.0998)
  curve K3 (-27.6071, -86.7521) -> (0, 0)
  curve K4 (0, -8.196) -> (0, 8.196)
  curve K5 (-28.8917, -95.7448) -> (-26.3224, -77.7593)
  point P1 (0, 0)
  point P2 (0, 0)
  point P3 (0, 27.0443)
  point P7 (-27.6071, -86.7521)
  coincident P1 P2
  vertical L1
  midpoint P3 K2
  vertical K2
  midpoint P2 K4
  vertical K4
  midpoint P7 K5
sweep "Sweep1" sketch "Sketch4" TwistAngle 0 TaperAngle 0
chamfer "Chamfer3" distance 0.5
chamfer "Chamfer4" distance 0.5
fillet "Fillet2" radius 2
fillet "Fillet3" radius 4 2
extrude "Extrude12" add of existing geometry to an object
combine "Combine5"
sketch "Sketch6" plane through (94, 0, 0) normal (1, 0, 0) x axis (0, 1, 0)
  line L1 (85, 2) -> (30, 2)
  line L2 (113, 150) -> (113, 30)
  line L3 (30, 178) -> (85, 178)
  line L4 (2, 30) -> (2, 150)
  line L5 (85, 170) -> (30, 170)
  line L6 (105, 30) -> (105, 150)
  line L7 (30, 10) -> (85, 10)
  line L8 (10, 150) -> (10, 30)
  line L9 (12, 150) -> (12, 30)
  line L10 (85, 168) -> (30, 168)
  line L11 (103, 30) -> (103, 150)
  line L12 (30, 12) -> (85, 12)
  arc A1 centre (85, 30) radius 28 clockwise from (113, 30) to (85, 2)
  arc A2 centre (85, 150) radius 28 clockwise from (85, 178) to (113, 150)
  arc A3 centre (30, 150) radius 28 clockwise from (2, 150) to (30, 178)
  arc A4 centre (30, 30) radius 28 clockwise from (30, 2) to (2, 30)
  arc A5 centre (30, 150) radius 20 clockwise from (10, 150) to (30, 170)
  arc A6 centre (85, 150) radius 20 clockwise from (85, 170) to (105, 150)
  arc A7 centre (85, 30) radius 20 clockwise from (105, 30) to (85, 10)
  arc A8 centre (30, 30) radius 20 clockwise from (30, 10) to (10, 30)
  arc A9 centre (30, 150) radius 18 clockwise from (12, 150) to (30, 168)
  arc A10 centre (85, 150) radius 18 clockwise from (85, 168) to (103, 150)
  arc A11 centre (85, 30) radius 18 clockwise from (103, 30) to (85, 12)
  arc A12 centre (30, 30) radius 18 clockwise from (30, 12) to (12, 30)
  dimension "d216" = -2
extrude "Extrude13" add sketch "Sketch6" profile of A5 L5 A6 L6 A7 L7 A8 L8 L10 A9 L9 L11 A10 A11 L12 A12 against normal blind 4
chamfer "Chamfer5" distance 2 distance 3
copy_paste_bodies "CopyPasteBodies1"
move "Move1"
delete_face "DeleteFace1"
copy_paste_bodies "CopyPasteBodies1"
move "Move1"
sketch "Sketch1" plane through (0, 0, 0) normal (-1, 0, 0) x axis (0, -1, 0)
  line L1 (-400, 150) -> (-400, 30)
  line L2 (-485, 180) -> (-430, 180)
  line L3 (-515, 30) -> (-515, 150)
  line L4 (-430, 0) -> (-485, 0)
  line L5 (-412.85, 56.5) -> (-412.85, 123.5)
  line L6 (-458, 12.35) -> (-457, 12.35)
  line L7 (-502.15, 123.5) -> (-502.15, 56.5)
  line L8 (-457, 167.65) -> (-458, 167.65)
  line L9 (-501.4142, 19.9497) -> (-502.8284, 18.5355)
  line L10 (-495.0503, 16.4142) -> (-498.5858, 19.9497)
  line L11 (-496.4645, 12.1716) -> (-495.0503, 13.5858)
  line L12 (-502.8284, 15.7071) -> (-499.2929, 12.1716)
  arc A1 centre (-430, 30) radius 30 clockwise from (-400, 30) to (-430, 0)
  arc A2 centre (-430, 150) radius 30 clockwise from (-430, 180) to (-400, 150)
  arc A3 centre (-485, 150) radius 30 clockwise from (-515, 150) to (-485, 180)
  arc A4 centre (-485, 30) radius 30 clockwise from (-485, 0) to (-515, 30)
  arc A5 centre (-457, 56.5) radius 44.15 clockwise from (-412.85, 56.5) to (-457, 12.35)
  arc A6 centre (-458, 56.5) radius 44.15 clockwise from (-458, 12.35) to (-502.15, 56.5)
  arc A7 centre (-458, 123.5) radius 44.15 clockwise from (-502.15, 123.5) to (-458, 167.65)
  arc A8 centre (-457, 123.5) radius 44.15 clockwise from (-457, 167.65) to (-412.85, 123.5)
  arc A9 centre (-500, 18.5355) radius 2 clockwise from (-501.4142, 19.9497) to (-498.5858, 19.9497)
  arc A10 centre (-496.4645, 15) radius 2 clockwise from (-495.0503, 16.4142) to (-495.0503, 13.5858)
  arc A11 centre (-497.8787, 13.5858) radius 2 clockwise from (-496.4645, 12.1716) to (-499.2929, 12.1716)
  arc A12 centre (-501.4142, 17.1213) radius 2 clockwise from (-502.8284, 15.7071) to (-502.8284, 18.5355)
extrude "Extrude1" add sketch "Sketch1" profile of L9 A9 L10 A10 L11 A11 L12 A12 against normal blind 38.684
sketch "Sketch2" plane through (0, 515, 0) normal (0, 1, 0) x axis (-1, 0, 0)
  line L1 (0, 150) -> (0, 30)
  line L2 (-106, 150) -> (0, 150)
  line L3 (-106, 30) -> (-106, 150)
  line L4 (0, 30) -> (-106, 30)
  line L5 (-53, 50.5086) -> (-53, 30)
  circle C1 centre (-62.75, 40) radius 3
  circle C2 centre (-43.25, 40) radius 3
  point P7 (-53, 30)
  point P6 (-62.75, 40)
  midpoint L4 P7
  perpendicular L4 L5
  symmetric C1 L5 C2
  dimension "d223" diameter C1 = 6
  dimension "d224" distance P6 L5 = 9.75
  dimension "d225" distance L4 P6 = 10
extrude "Extrude2" cut sketch "Sketch2" profile of C1 C2 against normal blind 10
sketch "Sketch7" plane through (0, 0, 0) normal (-1, 0, 0) x axis (0, -1, 0)
  line L1 (-302.8284, 15.7071) -> (-299.2929, 12.1716)
  line L2 (-301.4142, 19.9497) -> (-302.8284, 18.5355)
  line L3 (-295.0503, 16.4142) -> (-298.5858, 19.9497)
  line L4 (-296.4645, 12.1716) -> (-295.0503, 13.5858)
  line L5 (-285, 180) -> (-230, 180)
  line L6 (-315, 30) -> (-315, 150)
  line L7 (-230, 0) -> (-285, 0)
  line L8 (-200, 150) -> (-200, 30)
  line L9 (-315, 90) -> (-200, 90)
  arc A1 centre (-301.4142, 17.1213) radius 2 clockwise from (-302.8284, 15.7071) to (-302.8284, 18.5355)
  arc A2 centre (-300, 18.5355) radius 2 clockwise from (-301.4142, 19.9497) to (-298.5858, 19.9497)
  arc A3 centre (-296.4645, 15) radius 2 clockwise from (-295.0503, 16.4142) to (-295.0503, 13.5858)
  arc A4 centre (-297.8787, 13.5858) radius 2 clockwise from (-296.4645, 12.1716) to (-299.2929, 12.1716)
  arc A5 centre (-230, 150) radius 30 clockwise from (-230, 180) to (-200, 150)
  arc A6 centre (-285, 150) radius 30 clockwise from (-315, 150) to (-285, 180)
  arc A7 centre (-285, 30) radius 30 clockwise from (-285, 0) to (-315, 30)
  arc A8 centre (-230, 30) radius 30 clockwise from (-200, 30) to (-230, 0)
  circle C1 centre (-257.5, 90) radius 57
  circle C2 centre (-305.9665, 60) radius 1.35
  circle C3 centre (-305.9665, 120) radius 1.35
  circle C4 centre (-209.0335, 60) radius 1.35
  circle C5 centre (-209.0335, 120) radius 1.35
  circle C6 centre (-257.5, 147) radius 1.35
  circle C7 centre (-257.5, 33) radius 1.35
  circle C8 centre (-257.5, 90) radius 47.25
  point P26 (-200, 90)
  point P27 (-315, 90)
  point P30 (-257.5, 147)
  point P28 (-305.9665, 60)
  point P35 (-305.9665, 120)
  point P31 (-209.0335, 60)
  point P34 (-209.0335, 120)
  midpoint L8 P26
  midpoint L6 P27
  concentric C1 C8
  coincident P30 C1
  vertical P28 P35
  vertical P31 P34
  horizontal P28 P31
  horizontal P34 P35
  coincident P35 C1
  coincident P28 C1
  coincident P34 C1
  dimension "d228" diameter C8 = 94.5
  dimension "d229" diameter C1 = 114
  dimension "d230" diameter C6 = 2.7
  dimension "d269" distance P28 P35 = 60
extrude "Extrude14" cut sketch "Sketch7" profile of C2 C3 C4 C5 C6 C7 C8 against normal blind 15
chamfer "Chamfer6" distance 0.6
copy_paste_bodies "CopyPasteBodies2"
move "Move2"
extrude "Extrude15" sketch "Sketch2" profile of C1 C2 to an object
sketch "Sketch8" plane through (0, 0, 0) normal (-1, 0, 0) x axis (0, -1, 0)
  line L1 (-702.8284, 15.7071) -> (-699.2929, 12.1716)
  line L2 (-701.4142, 19.9497) -> (-702.8284, 18.5355)
  line L3 (-695.0503, 16.4142) -> (-698.5858, 19.9497)
  line L4 (-696.4645, 12.1716) -> (-695.0503, 13.5858)
  line L5 (-685, 180) -> (-630, 180)
  line L6 (-715, 30) -> (-715, 150)
  line L7 (-630, 0) -> (-685, 0)
  line L8 (-600, 150) -> (-600, 30)
  circle C1 centre (-657.5, 33) radius 1.95
  circle C2 centre (-609.0335, 120) radius 1.95
  circle C3 centre (-705.9665, 120) radius 1.95
  circle C4 centre (-657.5, 90) radius 47.25
  arc A1 centre (-701.4142, 17.1213) radius 2 clockwise from (-702.8284, 15.7071) to (-702.8284, 18.5355)
  arc A2 centre (-700, 18.5355) radius 2 clockwise from (-701.4142, 19.9497) to (-698.5858, 19.9497)
  arc A3 centre (-696.4645, 15) radius 2 clockwise from (-695.0503, 16.4142) to (-695.0503, 13.5858)
  arc A4 centre (-697.8787, 13.5858) radius 2 clockwise from (-696.4645, 12.1716) to (-699.2929, 12.1716)
  arc A5 centre (-630, 150) radius 30 clockwise from (-630, 180) to (-600, 150)
  arc A6 centre (-685, 150) radius 30 clockwise from (-715, 150) to (-685, 180)
  arc A7 centre (-685, 30) radius 30 clockwise from (-685, 0) to (-715, 30)
  arc A8 centre (-630, 30) radius 30 clockwise from (-600, 30) to (-630, 0)
  circle C5 centre (-657.5, 147) radius 1.95
  circle C6 centre (-705.9665, 60) radius 1.95
  circle C7 centre (-609.0335, 60) radius 1.95
extrude "Extrude16" add sketch "Sketch8" profile of L1 A1 L2 A2 L3 A3 L4 A4 against normal blind 37.581
align "Align6"
align "Align5"
chamfer "Chamfer2" distance 0.6
fillet "Fillet1" radius 0.6
chamfer "Chamfer3" distance 0.5 distance 1.5
copy_paste_bodies "CopyPasteBodies1"
move "Move1" TranslateX 200 TranslateY 0 TranslateZ 0
sketch "Sketch2" plane through (0, 2.2, 0) normal (0, -1, 0) x axis (1, 0, 0)
  line L1 (294.6, 30) -> (294.6, 150)
  line L2 (306, 30) -> (294.6, 30)
  line L3 (306, 150) -> (306, 30)
  line L4 (294.6, 150) -> (306, 150)
  line L5 (294, 90) -> (306, 90)
  line L6 (306, 90.4) -> (306, 90)
  line L7 (305.2, 90.85) -> (306, 90.4)
  line L8 (305.2, 91.15) -> (305.2, 90.85)
  line L9 (306, 91.6) -> (305.2, 91.15)
  line L10 (306, 92) -> (306, 91.6)
  line L11 (306.5, 92) -> (306.5, 90)
  line L12 (306.5, -5.51) -> (306.5, -7.51)
  line L13 (306, -5.51) -> (306, -5.91)
  line L14 (306, -5.91) -> (305.2, -6.36)
  line L15 (305.2, -6.36) -> (305.2, -6.66)
  line L16 (305.2, -6.66) -> (306, -7.11)
  line L17 (306, -7.11) -> (306, -7.51)
  line L18 (306.5, -3.52) -> (306.5, -5.52)
  line L19 (306, -3.52) -> (306, -3.92)
  line L20 (306, -3.92) -> (305.2, -4.37)
  line L21 (305.2, -4.37) -> (305.2, -4.67)
  line L22 (305.2, -4.67) -> (306, -5.12)
  line L23 (306, -5.12) -> (306, -5.52)
  line L24 (306.5, -1.53) -> (306.5, -3.53)
  line L25 (306, -1.53) -> (306, -1.93)
  line L26 (306, -1.93) -> (305.2, -2.38)
  line L27 (305.2, -2.38) -> (305.2, -2.68)
  line L28 (305.2, -2.68) -> (306, -3.13)
  line L29 (306, -3.13) -> (306, -3.53)
  line L30 (306.5, 0.46) -> (306.5, -1.54)
  line L31 (306, 0.46) -> (306, 0.06)
  line L32 (306, 0.06) -> (305.2, -0.39)
  line L33 (305.2, -0.39) -> (305.2, -0.69)
  line L34 (305.2, -0.69) -> (306, -1.14)
  line L35 (306, -1.14) -> (306, -1.54)
  line L36 (306.5, 2.45) -> (306.5, 0.45)
  line L37 (306, 2.45) -> (306, 2.05)
  line L38 (306, 2.05) -> (305.2, 1.6)
  line L39 (305.2, 1.6) -> (305.2, 1.3)
  line L40 (305.2, 1.3) -> (306, 0.85)
  line L41 (306, 0.85) -> (306, 0.45)
  line L42 (306.5, 4.44) -> (306.5, 2.44)
  line L43 (306, 4.44) -> (306, 4.04)
  line L44 (306, 4.04) -> (305.2, 3.59)
  line L45 (305.2, 3.59) -> (305.2, 3.29)
  line L46 (305.2, 3.29) -> (306, 2.84)
  line L47 (306, 2.84) -> (306, 2.44)
  line L48 (306.5, 6.43) -> (306.5, 4.43)
  line L49 (306, 6.43) -> (306, 6.03)
  line L50 (306, 6.03) -> (305.2, 5.58)
  line L51 (305.2, 5.58) -> (305.2, 5.28)
  line L52 (305.2, 5.28) -> (306, 4.83)
  line L53 (306, 4.83) -> (306, 4.43)
  line L54 (306.5, 8.42) -> (306.5, 6.42)
  line L55 (306, 8.42) -> (306, 8.02)
  line L56 (306, 8.02) -> (305.2, 7.57)
  line L57 (305.2, 7.57) -> (305.2, 7.27)
  line L58 (305.2, 7.27) -> (306, 6.82)
  line L59 (306, 6.82) -> (306, 6.42)
  line L60 (306.5, 10.41) -> (306.5, 8.41)
  line L61 (306, 10.41) -> (306, 10.01)
  line L62 (306, 10.01) -> (305.2, 9.56)
  line L63 (305.2, 9.56) -> (305.2, 9.26)
  line L64 (305.2, 9.26) -> (306, 8.81)
  line L65 (306, 8.81) -> (306, 8.41)
  line L66 (306.5, 12.4) -> (306.5, 10.4)
  line L67 (306, 12.4) -> (306, 12)
  line L68 (306, 12) -> (305.2, 11.55)
  line L69 (305.2, 11.55) -> (305.2, 11.25)
  line L70 (305.2, 11.25) -> (306, 10.8)
  line L71 (306, 10.8) -> (306, 10.4)
  line L72 (306.5, 14.39) -> (306.5, 12.39)
  line L73 (306, 14.39) -> (306, 13.99)
  line L74 (306, 13.99) -> (305.2, 13.54)
  line L75 (305.2, 13.54) -> (305.2, 13.24)
  line L76 (305.2, 13.24) -> (306, 12.79)
  line L77 (306, 12.79) -> (306, 12.39)
  line L78 (306.5, 16.38) -> (306.5, 14.38)
  line L79 (306, 16.38) -> (306, 15.98)
  line L80 (306, 15.98) -> (305.2, 15.53)
  line L81 (305.2, 15.53) -> (305.2, 15.23)
  line L82 (305.2, 15.23) -> (306, 14.78)
  line L83 (306, 14.78) -> (306, 14.38)
  line L84 (306.5, 18.37) -> (306.5, 16.37)
  line L85 (306, 18.37) -> (306, 17.97)
  line L86 (306, 17.97) -> (305.2, 17.52)
  line L87 (305.2, 17.52) -> (305.2, 17.22)
  line L88 (305.2, 17.22) -> (306, 16.77)
  line L89 (306, 16.77) -> (306, 16.37)
  line L90 (306.5, 20.36) -> (306.5, 18.36)
  line L91 (306, 20.36) -> (306, 19.96)
  line L92 (306, 19.96) -> (305.2, 19.51)
  line L93 (305.2, 19.51) -> (305.2, 19.21)
  line L94 (305.2, 19.21) -> (306, 18.76)
  line L95 (306, 18.76) -> (306, 18.36)
  line L96 (306.5, 22.35) -> (306.5, 20.35)
  line L97 (306, 22.35) -> (306, 21.95)
  line L98 (306, 21.95) -> (305.2, 21.5)
  line L99 (305.2, 21.5) -> (305.2, 21.2)
  line L100 (305.2, 21.2) -> (306, 20.75)
  line L101 (306, 20.75) -> (306, 20.35)
  line L102 (306.5, 24.34) -> (306.5, 22.34)
  line L103 (306, 24.34) -> (306, 23.94)
  line L104 (306, 23.94) -> (305.2, 23.49)
  line L105 (305.2, 23.49) -> (305.2, 23.19)
  line L106 (305.2, 23.19) -> (306, 22.74)
  line L107 (306, 22.74) -> (306, 22.34)
  line L108 (306.5, 26.33) -> (306.5, 24.33)
  line L109 (306, 26.33) -> (306, 25.93)
  line L110 (306, 25.93) -> (305.2, 25.48)
  line L111 (305.2, 25.48) -> (305.2, 25.18)
  line L112 (305.2, 25.18) -> (306, 24.73)
  line L113 (306, 24.73) -> (306, 24.33)
  line L114 (306.5, 28.32) -> (306.5, 26.32)
  line L115 (306, 28.32) -> (306, 27.92)
  line L116 (306, 27.92) -> (305.2, 27.47)
  line L117 (305.2, 27.47) -> (305.2, 27.17)
  line L118 (305.2, 27.17) -> (306, 26.72)
  line L119 (306, 26.72) -> (306, 26.32)
  line L120 (306.5, 30.31) -> (306.5, 28.31)
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  point P6 (306, 90)
  point P8 (306, 90.4)
  point P11 (306, 91.6)
  point P12 (306, 92)
  point P14 (306.5, 92)
  point P13 (306.5, 90)
  point P9 (305.2, 90.85)
  point P10 (305.2, 91.15)
  midpoint L3 P6
  perpendicular L1 L5
  coincident L3 P8
  parallel L6 L8
  coincident L3 P11
  parallel L3 L10
  perpendicular L5 L11
  horizontal P12 P14
  horizontal P6 P13
  dimension "d186" distance P6 P8 = 0.4
  dimension "d187" distance P9 P10 = 0.3
  dimension "d188" distance P8 P9 = 0.45
  dimension "d189" distance P10 P11 = 0.45
  dimension "d190" distance P11 P12 = 0.4
  dimension "d191" distance L3 L8 = 0.8
  dimension "d192" distance L3 L11 = 0.5
  dimension "d195" R-Pattern1-uDistance = 2
  dimension "d196" R-Pattern1-vDistance = 1.99
extrude "Extrude3" cut sketch "Sketch2" to an object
